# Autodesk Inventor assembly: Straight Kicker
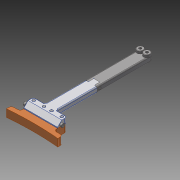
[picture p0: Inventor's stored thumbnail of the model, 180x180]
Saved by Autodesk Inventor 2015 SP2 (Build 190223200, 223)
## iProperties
Created: 2012-07
Part Number: Straight Kicker
Document SubType Name: Assembly
Designer: rYan
Mass: 73.1717 g
Surface Area: 106.049 cm^2
Volume: 17.1059 cm^3
Density: 4.27758 g/cm^3
Author: rYan
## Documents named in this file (7)
- D:\TIGERs GIT\Hardware\mechanik\2016\Inventor\Kicker\Straight\MG-Straight Kicker.iam
- D:\TIGERs GIT\Hardware\mechanik\2016\Inventor\Kicker\Straight\Kicker Vorne.ipt
- D:\TIGERs GIT\Hardware\mechanik\2016\Inventor\Kicker\Kicker Eisen.ipt
- D:\TIGERs GIT\Hardware\mechanik\2016\Inventor\Inhaltscenter\de-DE\ISO 2338(1)\ISO 2338 - 3 m6 x 12DIN EN.ipt
- D:\TIGERs GIT\Hardware\mechanik\2016\Inventor\Kicker\Kicker Mitte.ipt
- D:\TIGERs GIT\Hardware\mechanik\2016\Inventor\Inhaltscenter\de-DE\DIN 7984\DIN 7984 - M4 x 6.ipt
- D:\TIGERs GIT\Hardware\mechanik\2016\Inventor\Inhaltscenter\de-DE\ISO 4762(1)\ISO 4762 - M2 x 5DIN EN ISO.ipt
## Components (12 placed, 6 different names)
1. Kicker Vorne:1 — Passend:4, Passend:5, Passend:6
2. Kicker Eisen:1 — Passend:1, Fluchtend:1, Fluchtend:2, Passend:3, Fluchtend:5, Einfügen:1, Einfügen:2
3. Kicker Mitte:1 — Passend:1, Fluchtend:1, Fluchtend:2, Passend:4, Passend:5, Passend:6, Passend:7, Passend:8, Fluchtend:6, Fluchtend:7, Einfügen:5, Einfügen:6, Einfügen:7, Einfügen:8
4. DIN EN ISO 2338 3 m6 x 12:1 — Passend:3, Fluchtend:5
5. DIN EN ISO 2338 3 m6 x 12:2 — Passend:8, Fluchtend:7
6. DIN EN ISO 2338 3 m6 x 12:3 — Passend:7, Fluchtend:6
7. DIN 7984 M4 x 6:1 — Einfügen:2
8. DIN 7984 M4 x 6:2 — Einfügen:1
9. DIN EN ISO 2338 3 m6 x 12:4 — Einfügen:5
10. DIN EN ISO 2338 3 m6 x 12:5 — Einfügen:6
11. DIN EN ISO 4762 M2 x 5:3 — Einfügen:7
12. DIN EN ISO 4762 M2 x 5:4 — Einfügen:8
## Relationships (18: Mate 7, Insert 6, Flush 5)
- Passend:1 [Mate]: Kicker Eisen:1 ↔ Kicker Mitte:1
- Fluchtend:1 [Flush]: Kicker Eisen:1 ↔ Kicker Mitte:1
- Fluchtend:2 [Flush]: Kicker Eisen:1 ↔ Kicker Mitte:1
- Passend:3 [Mate]: Kicker Eisen:1 ↔ DIN EN ISO 2338 3 m6 x 12:1
- Fluchtend:5 [Flush]: Kicker Eisen:1 ↔ DIN EN ISO 2338 3 m6 x 12:1
- Passend:4 [Mate]: Kicker Vorne:1 ↔ Kicker Mitte:1
- Passend:5 [Mate]: Kicker Vorne:1 ↔ Kicker Mitte:1
- Passend:6 [Mate]: Kicker Vorne:1 ↔ Kicker Mitte:1
- Passend:7 [Mate]: Kicker Mitte:1 ↔ DIN EN ISO 2338 3 m6 x 12:3
- Passend:8 [Mate]: Kicker Mitte:1 ↔ DIN EN ISO 2338 3 m6 x 12:2
- Fluchtend:6 [Flush]: Kicker Mitte:1 ↔ DIN EN ISO 2338 3 m6 x 12:3
- Fluchtend:7 [Flush]: Kicker Mitte:1 ↔ DIN EN ISO 2338 3 m6 x 12:2
- Einfügen:1 [Insert]: Kicker Eisen:1 ↔ DIN 7984 M4 x 6:2
- Einfügen:2 [Insert]: Kicker Eisen:1 ↔ DIN 7984 M4 x 6:1
- Einfügen:5 [Insert]: Kicker Mitte:1 ↔ DIN EN ISO 2338 3 m6 x 12:4
- Einfügen:6 [Insert]: Kicker Mitte:1 ↔ DIN EN ISO 2338 3 m6 x 12:5
- Einfügen:7 [Insert]: Kicker Mitte:1 ↔ DIN EN ISO 4762 M2 x 5:3
- Einfügen:8 [Insert]: Kicker Mitte:1 ↔ DIN EN ISO 4762 M2 x 5:4
